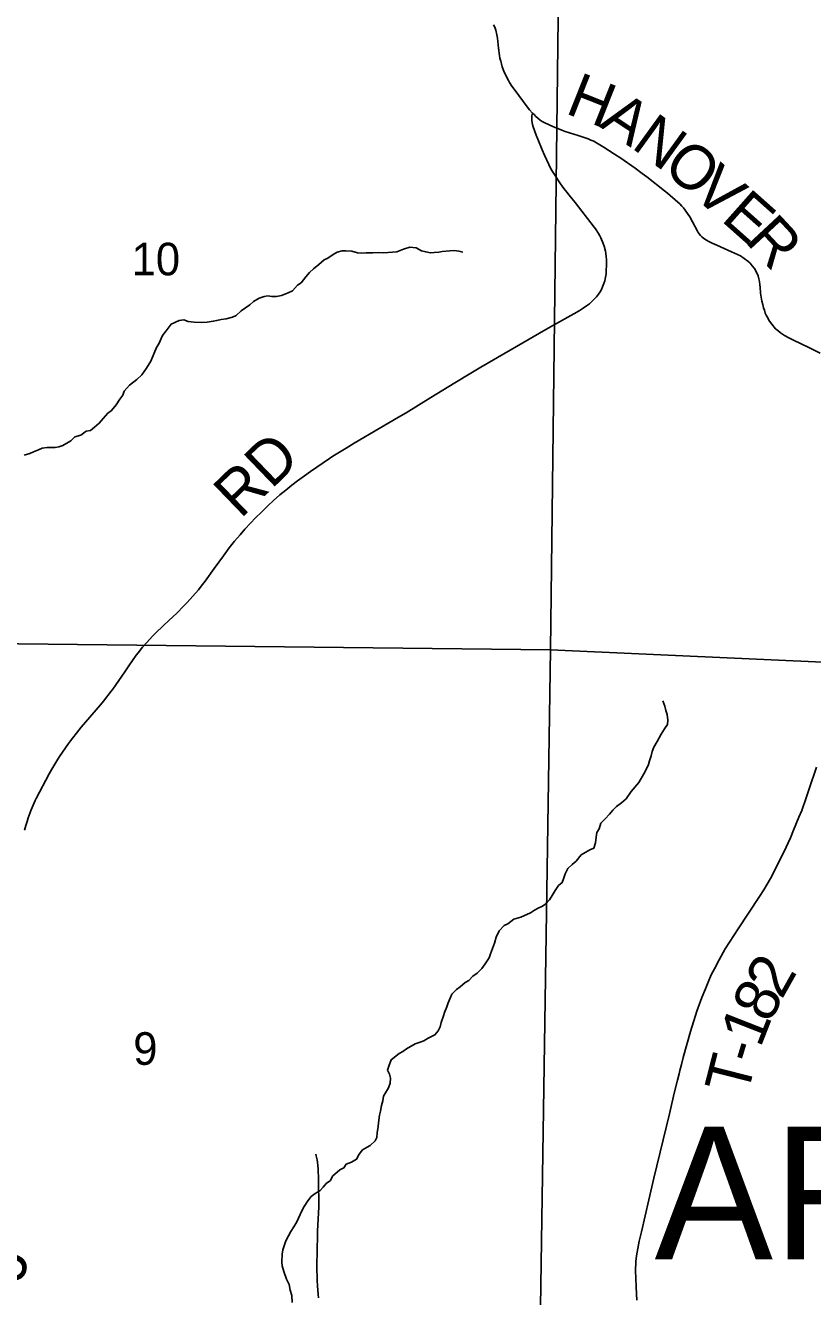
# Model space of a CAD drawing. Extents: x 0 to 34, y 0 to 22.
# Drawn here: x 13.784 to 14.795, y 15.132 to 16.764 of the extents above; entities that cross this region are included whole.
import ezdxf

# ---------------------------------------------------------------- set-up
doc = ezdxf.new("R2010")
doc.units = 0
for name, color, linetype in [('GM_X_Corporation', 7, 'Continuous'), ('GM_X_County_Road', 7, 'Continuous'), ('GM_X_County_Road_Text', 7, 'Continuous'), ('GM_X_Minor_River', 7, 'Continuous'), ('GM_X_Section_Text', 7, 'Continuous'), ('GM_X_Township_Road', 7, 'Continuous'), ('GM_X_Township_Road_Text', 7, 'Continuous'), ('GM_X_Township_Text', 7, 'Continuous')]:
    doc.layers.add(name, color=color, linetype=linetype)

msp = doc.modelspace()

# ---------------------------------------------------------------- linework, layer by layer
at = {"layer": 'GM_X_Corporation'}
for points in [[(13.4493, 16.9912), (14.4709, 16.9847), (14.4583, 15.9623), (13.4336, 15.974)], [(14.4709, 16.9847), (15.4816, 16.9282), (15.4691, 15.9163), (14.4583, 15.9623)], [(13.4336, 15.974), (14.4583, 15.9623), (14.443, 14.9501), (13.4208, 14.9679)], [(14.4583, 15.9623), (15.4691, 15.9163), (15.4475, 14.9085), (14.443, 14.9501)]]:
    msp.add_lwpolyline(points, close=True, dxfattribs=at)
at = {"layer": 'GM_X_County_Road'}
msp.add_lwpolyline([(14.3853, 16.7646), (14.3864, 16.7624), (14.3874, 16.7602), (14.3882, 16.7575), (14.3896, 16.7514), (14.3902, 16.7475), (14.3918, 16.7343), (14.3929, 16.7249), (14.3935, 16.7216), (14.3944, 16.7178), (14.3953, 16.7142), (14.3964, 16.7105), (14.3985, 16.7049), (14.4002, 16.7011), (14.4045, 16.6928), (14.4059, 16.6903), (14.4089, 16.6856), (14.4116, 16.6818), (14.4297, 16.6574), (14.4316, 16.6553), (14.4353, 16.6512), (14.4372, 16.6492), (14.4395, 16.6469), (14.4421, 16.6446), (14.445, 16.6422), (14.4475, 16.6405), (14.4501, 16.639), (14.4565, 16.6359), (14.4612, 16.6338), (14.4728, 16.6291), (14.4772, 16.6276), (14.4937, 16.6225), (14.503, 16.6194), (14.5068, 16.618), (14.5103, 16.6166), (14.5139, 16.6149), (14.5174, 16.613), (14.5259, 16.6078), (14.5403, 16.5986), (14.5486, 16.5931), (14.5669, 16.5804), (14.5761, 16.5738), (14.5818, 16.5695), (14.6047, 16.5515), (14.6085, 16.5482), (14.622, 16.5367), (14.6244, 16.5345), (14.6271, 16.5317), (14.6292, 16.5294), (14.6314, 16.5266), (14.6352, 16.521), (14.6371, 16.5179), (14.6469, 16.4995), (14.648, 16.4978), (14.6492, 16.4962), (14.651, 16.4941), (14.6528, 16.4923), (14.6553, 16.4902), (14.6584, 16.4881), (14.6606, 16.4868), (14.6658, 16.4843), (14.6719, 16.4815), (14.6909, 16.4732), (14.7021, 16.4678), (14.707, 16.4646), (14.7118, 16.461), (14.7146, 16.4584), (14.7174, 16.4552), (14.7201, 16.4515), (14.7232, 16.4463), (14.7249, 16.4421), (14.7259, 16.4386), (14.7267, 16.4351), (14.7272, 16.4309), (14.7274, 16.4277), (14.7281, 16.4202), (14.7287, 16.4151), (14.7296, 16.4098), (14.7307, 16.4056), (14.7319, 16.401), (14.7329, 16.398), (14.7339, 16.3945), (14.7353, 16.3918), (14.7363, 16.3897), (14.7395, 16.3842), (14.7424, 16.3802), (14.7473, 16.3744), (14.7501, 16.3719), (14.7537, 16.369), (14.7588, 16.3657), (14.7645, 16.3625), (14.7702, 16.3599), (14.7901, 16.3504), (14.8045, 16.3432)], dxfattribs=at)
at = {"layer": 'GM_X_Minor_River'}
for points in [[(14.1793, 16.4696), (14.1846, 16.4727), (14.1911, 16.4742), (14.1956, 16.4742), (14.2032, 16.4738), (14.2104, 16.4716), (14.2161, 16.4712), (14.2218, 16.4716), (14.2302, 16.472), (14.2374, 16.4724), (14.2446, 16.4716), (14.2556, 16.4728), (14.2613, 16.4732), (14.2697, 16.4766), (14.2776, 16.4789), (14.286, 16.4782), (14.2928, 16.4744), (14.2981, 16.4729), (14.3042, 16.4717), (14.3092, 16.4721), (14.3149, 16.4725), (14.3194, 16.4733), (14.3293, 16.4745), (14.3346, 16.4748), (14.3407, 16.4741), (14.3456, 16.4726)], [(13.7827, 16.2122), (13.7899, 16.2141), (13.7948, 16.2164), (13.8009, 16.2191), (13.8058, 16.221), (13.8123, 16.2221), (13.8225, 16.2221), (13.8271, 16.2229), (13.8324, 16.2244), (13.8426, 16.2305), (13.8479, 16.2358), (13.8555, 16.2378), (13.8623, 16.2427), (13.868, 16.2439), (13.8729, 16.248), (13.879, 16.253), (13.8843, 16.2591), (13.89, 16.2659), (13.8949, 16.2694), (13.9006, 16.2766), (13.9055, 16.2838), (13.9092, 16.2891), (13.9111, 16.2941), (13.9179, 16.302), (13.9274, 16.3093), (13.9338, 16.3154), (13.9399, 16.3237), (13.9452, 16.3329), (13.9474, 16.3378), (13.9497, 16.3431), (13.9527, 16.3503), (13.9557, 16.3549), (13.9602, 16.3655), (13.9648, 16.3716), (13.9712, 16.3804), (13.9818, 16.3849), (13.9875, 16.3857), (13.9932, 16.3838), (14.0008, 16.3827), (14.0099, 16.3823), (14.0175, 16.3827), (14.0255, 16.3839), (14.03, 16.385), (14.0357, 16.3862), (14.0418, 16.387), (14.0501, 16.3893), (14.0547, 16.3915), (14.0611, 16.3972), (14.0668, 16.4011), (14.0725, 16.4052), (14.077, 16.4094), (14.0842, 16.4136), (14.0907, 16.4159), (14.0956, 16.4167), (14.1005, 16.4159), (14.1066, 16.4156), (14.1131, 16.4171), (14.1218, 16.4205), (14.1271, 16.4232), (14.1335, 16.4304), (14.1381, 16.4331), (14.1441, 16.4411), (14.149, 16.4464), (14.1543, 16.4513), (14.1608, 16.4567), (14.168, 16.4628), (14.1725, 16.465), (14.1793, 16.4696)], [(14.2374, 15.3552), (14.2389, 15.365), (14.24, 15.37), (14.2415, 15.3776), (14.243, 15.3833), (14.2441, 15.3893), (14.2506, 15.4), (14.2524, 15.4061), (14.2528, 15.4125), (14.2516, 15.4178), (14.249, 15.4228), (14.2508, 15.4281), (14.2539, 15.4361), (14.2641, 15.4441), (14.269, 15.4467), (14.2736, 15.4502), (14.2845, 15.4566), (14.291, 15.4589), (14.2959, 15.4605), (14.3012, 15.4639), (14.3099, 15.4681), (14.3141, 15.4734), (14.3167, 15.4784), (14.3182, 15.4841), (14.3212, 15.4924), (14.3224, 15.497), (14.3254, 15.5042), (14.3269, 15.5091), (14.3295, 15.5152), (14.3318, 15.5202), (14.3378, 15.5263), (14.3424, 15.5297), (14.3488, 15.5354), (14.3534, 15.5377), (14.3587, 15.5434), (14.3643, 15.5472), (14.3704, 15.5533), (14.3746, 15.5594), (14.3795, 15.567), (14.3813, 15.5723), (14.384, 15.5791), (14.3866, 15.5856), (14.3885, 15.5936), (14.3926, 15.6015), (14.3987, 15.6084), (14.4036, 15.6107), (14.4112, 15.6164), (14.4203, 15.6191), (14.4328, 15.6248), (14.4377, 15.6282), (14.4427, 15.6305), (14.448, 15.6332), (14.4525, 15.6362), (14.457, 15.6415), (14.4604, 15.6469), (14.4642, 15.6533), (14.4688, 15.6598), (14.4733, 15.6636), (14.4752, 15.6685), (14.4771, 15.6746), (14.4808, 15.6815), (14.4861, 15.6868), (14.4911, 15.691), (14.4979, 15.699), (14.5088, 15.7054), (14.5138, 15.7077), (14.516, 15.7146), (14.5171, 15.7218), (14.5179, 15.7279), (14.5209, 15.7324), (14.5228, 15.7397), (14.5285, 15.7454), (14.5341, 15.7514), (14.5383, 15.7564), (14.5432, 15.761), (14.5496, 15.7659), (14.5553, 15.7712), (14.5617, 15.7804), (14.5716, 15.7921), (14.578, 15.8032), (14.5814, 15.8096), (14.584, 15.8153), (14.5855, 15.8199), (14.5874, 15.8264), (14.5889, 15.8317), (14.5912, 15.8374), (14.5953, 15.8446), (14.598, 15.8495), (14.6006, 15.8541), (14.6048, 15.8609), (14.6085, 15.8666), (14.6089, 15.872), (14.6081, 15.8792), (14.6066, 15.8845), (14.605, 15.8898), (14.6027, 15.8966)], [(14.1269, 15.1248), (14.1261, 15.1335), (14.1242, 15.1403), (14.1227, 15.1475), (14.1196, 15.1547), (14.1162, 15.1642), (14.1139, 15.1718), (14.1135, 15.1764), (14.1138, 15.1866), (14.1149, 15.192), (14.1164, 15.1973), (14.1187, 15.2038), (14.1221, 15.2102), (14.1251, 15.2159), (14.1289, 15.2216), (14.1327, 15.2281), (14.1391, 15.2422), (14.1421, 15.2479), (14.147, 15.2551), (14.1512, 15.2608), (14.1561, 15.2646), (14.1621, 15.268), (14.1667, 15.2726), (14.1705, 15.2772), (14.1758, 15.2813), (14.1784, 15.2867), (14.1879, 15.2947), (14.1932, 15.2973), (14.1962, 15.3023), (14.203, 15.3049), (14.2095, 15.3084), (14.2129, 15.3148), (14.217, 15.3205), (14.2269, 15.3259), (14.2333, 15.332), (14.2356, 15.3365), (14.2359, 15.3422), (14.2371, 15.3506), (14.2374, 15.3552)]]:
    msp.add_lwpolyline(points, dxfattribs=at)
at = {"layer": 'GM_X_Township_Road'}
for points in [[(13.7832, 15.7307), (13.7848, 15.737), (13.7864, 15.742), (13.788, 15.7468), (13.7919, 15.7568), (13.7969, 15.769), (13.7981, 15.7716), (13.8149, 15.8033), (13.8182, 15.8092), (13.8245, 15.8199), (13.8281, 15.8254), (13.8396, 15.8419), (13.8422, 15.8455), (13.8527, 15.8592), (13.856, 15.8632), (13.8805, 15.8917), (13.8845, 15.8965), (13.8944, 15.909), (13.8966, 15.9119), (13.9119, 15.9342), (13.917, 15.9418), (13.9266, 15.9555), (13.929, 15.9586), (13.9347, 15.9658), (13.94, 15.9717), (13.9474, 15.9797), (13.9509, 15.9832), (13.962, 15.9938), (13.9741, 16.0051), (13.9783, 16.009), (13.9883, 16.0191), (13.9921, 16.0231), (13.9993, 16.0311), (14.0063, 16.0393), (14.01, 16.0439), (14.0151, 16.0506), (14.0265, 16.0666), (14.0384, 16.0831), (14.0459, 16.0931), (14.0529, 16.1019), (14.0598, 16.11), (14.0661, 16.1172), (14.0732, 16.1248), (14.0796, 16.1315), (14.0877, 16.1395), (14.0956, 16.1471), (14.1029, 16.1538), (14.111, 16.161), (14.1186, 16.1673), (14.1263, 16.1735), (14.1336, 16.179), (14.1424, 16.1854), (14.1504, 16.1911), (14.1747, 16.2078), (14.1791, 16.2107), (14.1959, 16.2213), (14.2065, 16.2277), (14.2386, 16.2462), (14.2633, 16.2607), (14.273, 16.2665), (14.3049, 16.2863), (14.3356, 16.3051), (14.356, 16.3174), (14.3691, 16.3251), (14.4523, 16.3733), (14.4624, 16.3788), (14.4881, 16.3935), (14.495, 16.3975), (14.5002, 16.4008), (14.5046, 16.4037), (14.5082, 16.4065), (14.5114, 16.4093), (14.5147, 16.4126), (14.5173, 16.4155), (14.5199, 16.4188), (14.5219, 16.4218), (14.5236, 16.4249), (14.5252, 16.4283), (14.5268, 16.4323), (14.5279, 16.4357), (14.5286, 16.4384), (14.5297, 16.4449), (14.53, 16.4477), (14.5303, 16.4571), (14.5302, 16.4627), (14.53, 16.4672), (14.5295, 16.4711), (14.529, 16.4741), (14.5273, 16.4805), (14.5261, 16.4838), (14.5231, 16.4909), (14.5217, 16.4938), (14.52, 16.4966), (14.5163, 16.5024), (14.5145, 16.5049), (14.4898, 16.5365), (14.4825, 16.5456), (14.4793, 16.5497), (14.4756, 16.5545), (14.4713, 16.5603), (14.4677, 16.5656), (14.4642, 16.5709), (14.461, 16.5761), (14.4585, 16.5806), (14.4561, 16.5852), (14.4505, 16.5973), (14.4475, 16.604), (14.4419, 16.6176), (14.44, 16.6228), (14.4362, 16.6336), (14.4354, 16.6365), (14.4344, 16.6412), (14.4342, 16.6428), (14.4343, 16.6463), (14.4345, 16.6478), (14.4353, 16.6512)], [(14.669, 15.553), (14.675, 15.5644), (14.6824, 15.5784), (14.6991, 15.6042), (14.7267, 15.6455), (14.7324, 15.6541), (14.7407, 15.6687), (14.7469, 15.6802), (14.7533, 15.6938), (14.7577, 15.7026), (14.7664, 15.7211), (14.7703, 15.7309), (14.7772, 15.7473), (14.7808, 15.7562), (14.7866, 15.7725), (14.7906, 15.784), (14.7996, 15.8116)], [(14.5692, 15.1277), (14.5683, 15.1443), (14.5679, 15.1563), (14.5676, 15.1647), (14.568, 15.1774), (14.5689, 15.1844), (14.5705, 15.1937), (14.5723, 15.2031), (14.575, 15.2151), (14.5846, 15.2563), (14.5912, 15.284), (14.6112, 15.3666), (14.6143, 15.3802), (14.6177, 15.3949), (14.6213, 15.4099), (14.6233, 15.418), (14.6245, 15.4224), (14.6265, 15.4301), (14.6287, 15.4391), (14.638, 15.4724), (14.6461, 15.4983), (14.6527, 15.5162), (14.6571, 15.527), (14.6607, 15.5359), (14.6648, 15.545), (14.669, 15.553)], [(14.1605, 15.1305), (14.1599, 15.1349), (14.1591, 15.1458), (14.1588, 15.153), (14.1582, 15.1718), (14.1591, 15.211), (14.1594, 15.2162), (14.1606, 15.2398), (14.1608, 15.247), (14.1606, 15.2829), (14.1601, 15.2957), (14.1597, 15.3004), (14.1592, 15.3048), (14.1587, 15.3079), (14.1576, 15.3128), (14.157, 15.315)]]:
    msp.add_lwpolyline(points, dxfattribs=at)

# ---------------------------------------------------------------- texts
at = {"layer": 'GM_X_County_Road_Text'}
for s, rotation, p in [('H', 338.3576, (14.4758, 16.6515)), ('A', 326.5666, (14.5195, 16.6345)), ('N', 324.0948, (14.5607, 16.6073)), ('O', 320.3008, (14.6004, 16.5786)), ('V', 318.5002, (14.6385, 16.547)), ('E', 318.4081, (14.676, 16.5139)), ('R', 312.9214, (14.7067, 16.4867))]:
    msp.add_text(s, height=0.0568, rotation=rotation, dxfattribs=at).set_placement(p)
at = {"layer": 'GM_X_Section_Text'}
for s, height, p in [('10', 0.04186, (13.9206, 16.4429)), ('9', 0.0419, (13.9227, 15.4296))]:
    msp.add_text(s, height=height, rotation=0, dxfattribs=at).set_placement(p)
at = {"layer": 'GM_X_Township_Road_Text'}
for s, height, rotation, p in [('RD', 0.05682, 43.9584, (14.0604, 16.1295)), ('2', 0.0568, 60.7018, (14.7551, 15.5124)), ('8', 0.0568, 63.6491, (14.7399, 15.4817)), ('1', 0.0568, 68.5687, (14.7276, 15.4503)), ('-', 0.0568, 73.0981, (14.7212, 15.4291)), ('T', 0.0568, 75.7143, (14.7109, 15.3886)), ('6', 0.0568, 74.8467, (13.7789, 15.1438))]:
    msp.add_text(s, height=height, rotation=rotation, dxfattribs=at).set_placement(p)
at = {"layer": 'GM_X_Township_Text'}
msp.add_text('ARCHER', height=0.17045, rotation=0, dxfattribs=at).set_placement((14.5919, 15.1799))

doc.saveas('drawing.dxf')
